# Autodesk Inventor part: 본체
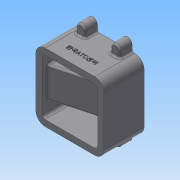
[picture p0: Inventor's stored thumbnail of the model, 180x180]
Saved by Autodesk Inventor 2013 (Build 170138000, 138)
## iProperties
Created: 2018-01
Part Number: 본체
Material: 일반
Document SubType Name: Modeling
Designer: Administrator
Density: 1 g/cm^3
Author: Administrator
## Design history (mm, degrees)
sketch "스케치1"
  geometry: L1 (-55, 55)-(55, 55); L2 (55, 55)-(55, -55); L3 (55, -55)-(-55, -55); L4 (-55, -55)-(-55, 55); L5 (45, -45)-(45, 45); L6 (45, 45)-(-45, 45); L7 (-45, 45)-(-45, -45); L8 (-45, -45)-(45, -45); 3 further points
  constraints: 16 end point, 4 parallel, 2 midpoint, 2 perpendicular, 1 horizontal, 1 horizontal alignment, 1 vertical alignment, 3 other
  dimensions: "d0" = 110 distance of L1.start L1.end; "d2" = 110 distance of L1.end L2.end; "d3" = 10 distance between parallel lines of L2 L5
extrude "돌출1" new body sketch "스케치1" stored distance "d4" = 65; taper "d5" = 0 deg
sketch "스케치2"
  geometry: L1 (-55, -55)-(-55, 55) reference; L2 (-55, 55)-(55, 55) reference; L3 (55, 55)-(55, -55) reference; L4 (55, -55)-(-55, -55) reference; L5 (-35.5, 65)-(-35.5, 55); L6 (-20.5, 65)-(-20.5, 55); L7 (-35.5, 55)-(-20.5, 55); L8 (0, 0)-(0, 45); L9 (0, 0)-(45, 0); A1 r 7.5 centre (-28, 65) between (-20.5, 65) and (-35.5, 65)
  constraints: 10 end point, 2 perpendicular, 2 point on circle, 2 point on line, 2 tangent, 1 centre point, 1 collinear
  dimensions: "d6" = 15 diameter of A1; "d7" = 27 distance from line of A1.centre L1; "d8" = 10 distance from line of A1.centre L2
extrude "돌출2" join sketch "스케치2" distance "d9" = 20; taper "d10" = 0 deg
sketch "스케치3"
  geometry: L1 (-110, 65)-(0, 65) reference; C1 r 7.5 at (-55, 65); 2 further points
  constraints: 2 midpoint, 1 centre point, 1 vertical alignment
  dimensions: "d11" = 15 diameter of C1
extrude "돌출3" cut sketch "스케치3" distance "d12" = 19; taper "d13" = 0 deg
sketch "스케치4"
  geometry: L1 (-55, 55)-(-35.5, 55) reference; L2 (-35.5, 55)-(-35.5, 65) reference; L3 (-20.5, 65)-(-20.5, 55) reference; L4 (-20.5, 55)-(20.5, 55) reference; L5 (20.5, 55)-(20.5, 65) reference; L6 (35.5, 65)-(35.5, 55) reference; L7 (35.5, 55)-(55, 55) reference; L8 (55, 55)-(55, -55) reference; L9 (55, -55)-(35.5, -55) reference; L10 (35.5, -55)-(35.5, -65) reference; L11 (20.5, -65)-(20.5, -55) reference; L12 (20.5, -55)-(-20.5, -55) reference; L13 (-20.5, -55)-(-20.5, -65) reference; L14 (-35.5, -65)-(-35.5, -55) reference; L15 (-35.5, -55)-(-55, -55) reference; L16 (-55, -55)-(-55, -7.5) reference; L17 (-55, -7.5)-(-36, -7.5) reference; L18 (-36, -7.5)-(-36, 7.5) reference; L19 (-36, 7.5)-(-55, 7.5) reference; L20 (-55, 7.5)-(-55, 55) reference; L21 (-45, 45)-(45, 45); L22 (45, 45)-(45, -45); L23 (45, -45)-(-45, -45); L24 (-45, -45)-(-45, 45); L25 (-45, 25)-(35, 25); L26 (35, 25)-(35, -25); L27 (35, -25)-(-45, -25); L28 (-45, -25)-(-45, 25); A1 r 7.5 centre (-28, 65) between (-20.5, 65) and (-35.5, 65) reference; A2 r 7.5 centre (28, 65) between (35.5, 65) and (20.5, 65) reference; A3 r 7.5 centre (28, -65) between (20.5, -65) and (35.5, -65) reference; A4 r 7.5 centre (-28, -65) between (-35.5, -65) and (-20.5, -65) reference; 4 further points
  constraints: 16 end point, 4 parallel, 3 midpoint, 2 horizontal, 2 horizontal alignment, 2 perpendicular, 1 collinear, 1 vertical alignment
  dimensions: "d14" = 10 distance between parallel lines of L24 L20; "d15" = 10 distance between parallel lines of L21 L4; "d16" = 30 distance between parallel lines of L25 L4; "d17" = 20 distance between parallel lines of L8 L26
extrude "돌출4" cut sketch "스케치4" stored distance "d18" = 19; taper "d19" = 0 deg
sketch "스케치5"
  geometry: L1 (-100, 65)-(-100, 0) reference; L2 (-100, 0)-(-110, 0) reference; L3 (-110, 0)-(-110, 65) reference; L4 (-110, 65)-(-100, 65) reference; L5 (-10, 0)-(-10, 65) reference; L6 (-10, 65)-(0, 65) reference; L7 (0, 65)-(0, 0) reference; L8 (0, 0)-(-10, 0) reference; L9 (-62.5, 65)-(-47.5, 65) reference; L10 (-80, 65)-(-62.5, 65) reference; L11 (-80, 0)-(-80, 65) reference; L12 (-30, 0)-(-80, 0) reference; L13 (-30, 65)-(-30, 0) reference; L14 (-47.5, 65)-(-30, 65) reference; C1 r 16 at (-55, 65); A1 r 7.5 centre (-55, 65) between (-62.5, 65) and (-47.5, 65) reference; 1 further point
  constraints: 1 centre point, 1 coincident
  dimensions: "d20" = 32 diameter of C1
extrude "돌출5" cut sketch "스케치5" distance "d21" = 14; taper "d22" = 0 deg
sketch "스케치6"
  geometry: L1 (-71, 65)-(-39, 65) reference; L2 (-80, 65)-(-71, 65) reference; L3 (-80, 0)-(-80, 65) reference; L4 (-30, 0)-(-80, 0) reference; L5 (-30, 65)-(-30, 0) reference; L6 (-39, 65)-(-30, 65) reference; L7 (-10, 65)-(14.5, 65) reference; L8 (14.5, 65)-(14.5, 45) reference; L9 (14.5, 45)-(0, 45) reference; L10 (0, 45)-(0, 0) reference; L11 (0, 0)-(-10, 0) reference; L12 (-10, 0)-(-10, 65) reference; L13 (-110, 0)-(-110, 45) reference; L14 (-110, 45)-(-124.5, 45) reference; L15 (-124.5, 45)-(-124.5, 65) reference; L16 (-124.5, 65)-(-100, 65) reference; L17 (-100, 65)-(-100, 0) reference; L18 (-100, 0)-(-110, 0) reference; C1 r 20 at (-55, 65); A1 r 16 centre (-55, 65) between (-71, 65) and (-39, 65) reference; 1 further point
  constraints: 1 centre point, 1 coincident
  dimensions: "d23" = 40 diameter of C1
extrude "돌출6" cut sketch "스케치6" distance "d24" = 47; taper "d25" = 0 deg
sketch "스케치7"
  geometry: L1 (-75, 65)-(-35, 65) reference; L2 (-80, 65)-(-75, 65) reference; L3 (-80, 0)-(-80, 65) reference; L4 (-30, 0)-(-80, 0) reference; L5 (-30, 65)-(-30, 0) reference; L6 (-35, 65)-(-30, 65) reference; L7 (-126.874, 65)-(-100, 65) reference; L8 (-100, 65)-(-100, 0) reference; L9 (-100, 0)-(-110, 0) reference; L10 (-110, 0)-(-110, 45) reference; L11 (-110, 45)-(-126.874, 45) reference; L12 (-126.874, 45)-(-126.874, 65) reference; L13 (-10, 65)-(16.874, 65) reference; L14 (16.874, 65)-(16.874, 45) reference; L15 (16.874, 45)-(0, 45) reference; L16 (0, 45)-(0, 0) reference; L17 (0, 0)-(-10, 0) reference; L18 (-10, 0)-(-10, 65) reference; C1 r 15 at (-55, 65); A1 r 20 centre (-55, 65) between (-75, 65) and (-35, 65) reference; 1 further point
  constraints: 1 centre point, 1 coincident
  dimensions: "d26" = 30 diameter of C1
extrude "돌출7" cut sketch "스케치7" distance "d27" = 5; taper "d28" = 0 deg
sketch "스케치8"
  geometry: L1 (-10, 0)-(0, 0) reference; L2 (0, 0)-(80, 0) reference; L3 (80, 0)-(80, -65) reference; L4 (80, -65)-(0, -65) reference; L5 (0, -65)-(-10, -65) reference; L6 (-10, -65)-(-10, 0) reference; L7 (0, 0)-(0, -65) reference; L8 (90, 0)-(100, 0) reference; L9 (100, 0)-(100, -65) reference; L10 (100, -65)-(90, -65) reference; L11 (90, -65)-(90, 0) reference; L12 (80, -35)-(0, -56.436); L13 (0, -56.436)-(0, -65); L14 (0, -65)-(80, -65); L15 (80, -65)-(80, -35); 1 further point
  constraints: 8 end point, 3 collinear, 2 point on line
  dimensions: "d29" = 105 deg angle of L12 L7; "d30" = 30 distance from line of L12.start L10
extrude "돌출8" cut sketch "스케치8" stored distance "d31" = 5; taper "d32" = 0 deg
sketch "스케치9"
  geometry: L1 (35, -2.5)-(-45, -23.936) reference; L2 (20, -1.343)-(-55, -21.439); L3 (-17, 6.743)-(-55, -3.439); L4 (-55, 32.5)-(-55, -32.5) reference; L5 (-22, 16.5)-(-22, 32.5) reference; L6 (25, 17.5)-(25, 32.5) reference; L7 (-17, 6.743)-(-17, 32.5); L8 (20, -1.343)-(20, 32.5); L9 (-17, 32.5)-(20, 32.5); L10 (-55, -3.439)-(-55, -21.439); 1 further point
  constraints: 12 end point, 4 parallel, 2 point on line, 1 collinear, 1 perpendicular
  dimensions: "d33" = 5 distance between parallel lines of L2 L1; "d34" = 18 distance of L3.end L2.end; "d35" = 5 distance between parallel lines of L8 L6; "d36" = 5 distance between parallel lines of L5 L7; "d37" = 25.75698 distance of L3.start L7.end
extrude "돌출9" cut sketch "스케치9" stored distance "d38" = 30; taper "d39" = 0 deg
hole "구멍1" diameter "d42" = 3.242; stored, may be unused: countersink angle "d46" = 90 deg, drill point angle "d48" = 118 deg; dims "d40" = 10, "d41" = 10, "d43" = 9, "d44" = 4, "d45" = 2, "d47" = 11
sketch "스케치10"
  geometry: L1 (110, 0)-(0, 0) reference; L2 (0, 65)-(0, 0) reference; 2 further points
  constraints: 1 other
  dimensions: "d49" = 20 distance from line of point (55, 20) L1; "d50" = 55 distance from line of point (55, 20) L2
feature "엠보싱1" sketch "스케치10" dims "d0" = 110, "d2" = 110, "d3" = 10, "d51" = 0.5, "d52" = 0
fillet "모깎기1" dims "d53" = 15
fillet "모깎기2" dims "d54" = 5
fillet "모깎기4" dims "d56" = 1
chamfer "모따기1" distance "d57" = 1; stored, may be unused: second distance "d58" = 2, angle "d59" = 45 deg
fillet "모깎기5" dims "d60" = 3
fillet "모깎기6" dims "d61" = 3
fillet "모깎기7" dims "d62" = 3
fillet "모깎기8" dims "d63" = 3
fillet "모깎기10" dims "d65" = 3
fillet "모깎기11" dims "d66" = 3
fillet "모깎기12" dims "d67" = 3
fillet "모깎기13" dims "d68" = 3
node "솔리드1"
mirror "대칭1"
mirror "대칭2"
mirror "대칭3"
mirror "대칭4"
node "절단 모서리 투영1"
node "절단 모서리 투영2"
node "절단 모서리 투영3"
node "절단 모서리 투영4"
node "절단 모서리 투영5"
node "절단 모서리 투영6"
